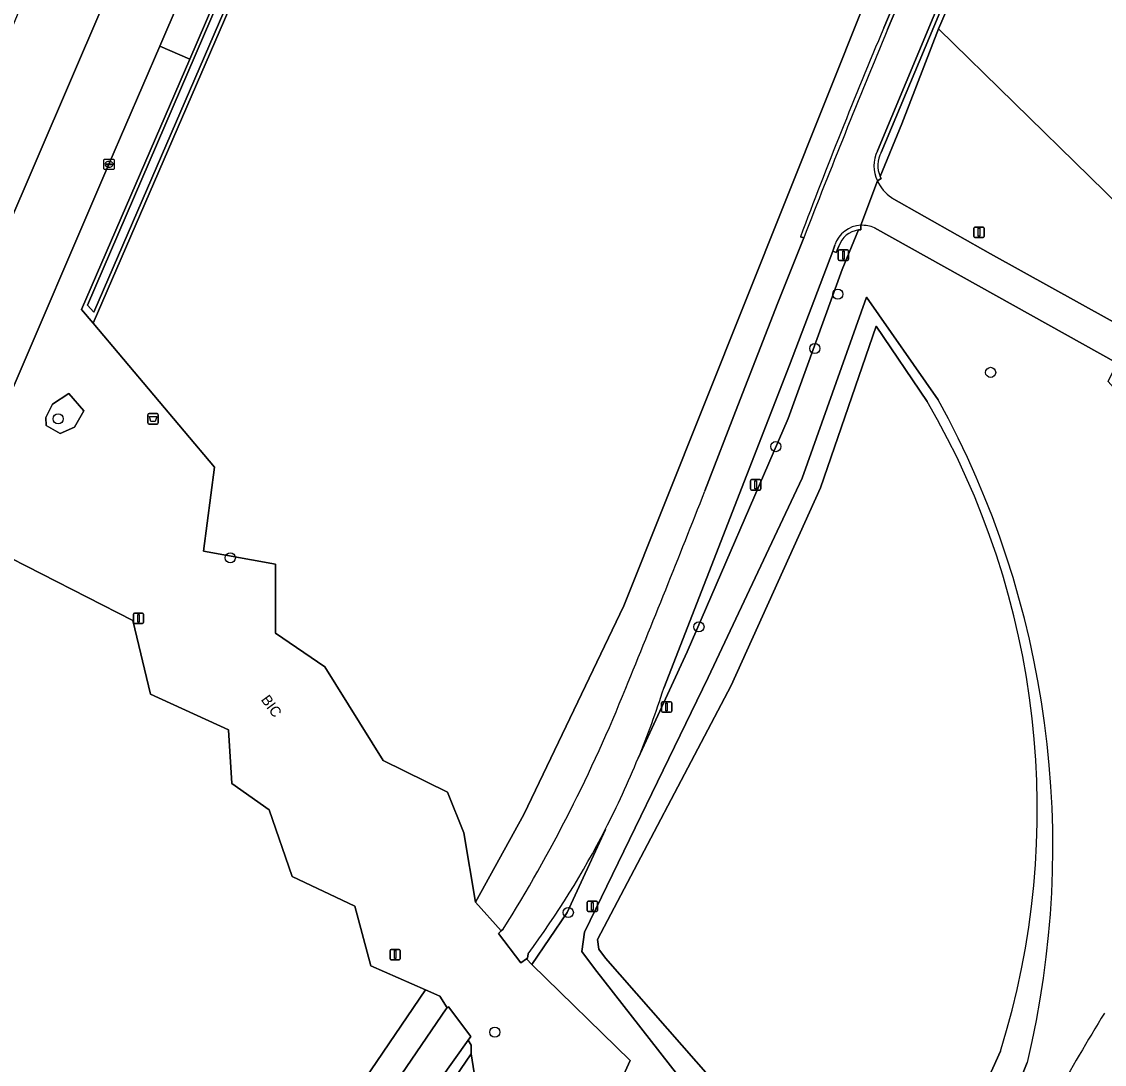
# Model space of a CAD drawing. Extents: x 155209 to 156748, y 385356 to 388487.
# Drawn here: x 155935.8 to 156040.2, y 385937.7 to 386038.3 of the extents above; entities that cross this region are included whole.
import ezdxf

# ---------------------------------------------------------------- set-up
doc = ezdxf.new("R2010")
doc.units = 0
for name, color, linetype in [('IMGEO_Afvalbak', 7, 'Continuous'), ('IMGEO_Berm_groen', 7, 'Continuous'), ('IMGEO_Berm_open', 7, 'Continuous'), ('IMGEO_Boom', 7, 'Continuous'), ('IMGEO_Fietspad_gesloten', 7, 'Continuous'), ('IMGEO_Groenvoorziening', 7, 'Continuous'), ('IMGEO_Kolk', 7, 'Continuous'), ('IMGEO_Lichtmast', 7, 'Continuous'), ('IMGEO_Loofbos', 7, 'Continuous'), ('IMGEO_Meer_plas_ven_vijver', 7, 'Continuous'), ('IMGEO_Naaldbos', 7, 'Continuous'), ('IMGEO_Oever', 7, 'Continuous'), ('IMGEO_Openbare_ruimte_label', 7, 'Continuous'), ('IMGEO_Rijbaan_lokaal_gesloten', 7, 'Continuous'), ('IMGEO_Voetpad_gesloten', 7, 'Continuous'), ('IMGEO_Voetpad_open', 7, 'Continuous'), ('IMGEO_Waterloop', 7, 'Continuous')]:
    doc.layers.add(name, color=color, linetype=linetype)

msp = doc.modelspace()

# ---------------------------------------------------------------- linework, layer by layer
at = {"layer": 'IMGEO_Afvalbak'}
for p, q in [((155948, 385999.57), (155948, 386000.37)), ((155948, 386000.37), (155948, 385999.57)), ((155948.1, 386000.47), (155948.89, 386000.47)), ((155948.89, 386000.47), (155948.1, 386000.47)), ((155948.99, 386000.37), (155948.99, 385999.57)), ((155948.99, 385999.57), (155948.99, 386000.37)), ((155948.89, 385999.47), (155948.1, 385999.47)), ((155948.1, 385999.47), (155948.89, 385999.47))]:
    msp.add_line(p, q, dxfattribs=at)
msp.add_lwpolyline([(155948.14, 386000.18), (155948.85, 386000.18), (155948.7, 385999.71), (155948.29, 385999.71), (155948.14, 386000.18)], dxfattribs=at)
for centre, start, end in [((155948.1, 386000.37), 90, 180), ((155948.1, 386000.37), 90, 180), ((155948.89, 386000.37), 0, 90), ((155948.89, 386000.37), 360, 90), ((155948.1, 385999.57), 180, 270), ((155948.1, 385999.57), 180, 270), ((155948.89, 385999.57), 270, 0), ((155948.89, 385999.57), 270, 0)]:
    msp.add_arc(centre, 0.1, start, end, dxfattribs=at)
at = {"layer": 'IMGEO_Berm_groen'}
for points in [[(156017.72, 386241.8), (155997.34, 386192.47), (155999.28, 386187.65), (155999.02, 386187.05), (155959.3, 386096.17), (155916.98, 385994.93), (155916.27, 385993.23), (155920.08, 385991.51), (155920.81, 385993.21), (155925.38, 386003.82), (155927.74, 386002.82), (155959.53, 386076.88), (155989.7, 386147.22), (156003.54, 386179.53)], [(156049.55, 386158.86), (156049.35, 386159.56), (156025.31, 386175.19), (156018.61, 386179.53), (156012.19, 386182.98), (156009.84, 386177.42), (156009.58, 386176.82), (155984.91, 386119.23), (155965.64, 386074.34), (155949.14, 386035.92), (155952.02, 386034.68), (156000, 386146)], [(156018.62, 386023.35), (156020.7, 386028.43), (156024.22, 386037.59), (156045.81, 386087.34), (156049.5, 386095.21), (156057.59, 386112.46), (156071.11, 386138.48), (156074.02, 386139.6), (156094.02, 386125.25), (156093.82, 386127.35), (156092.18, 386130.24), (156078.71, 386139.75)], [(156042.89, 386082.44), (156038.86, 386073.22), (156030.85, 386054.72), (156018.71, 386025.67)], [(156027.62, 386063.6), (156017.22, 386040.43), (155993.88, 385981.94), (155984.26, 385961.78), (155979.58, 385953.33), (155982.07, 385950.57), (155982.25, 385950.72)], [(156018.96, 386037.69), (156023.47, 386048.35), (156027.93, 386058.88), (156029.15, 386061.75), (156028.19, 386062.62), (156028.36, 386063)], [(156008.73, 386011.15), (156011.24, 386017.42), (156010.92, 386017.54)], [(156001.71, 385993.01), (156004.89, 386001.24), (156008.73, 386011.15)], [(155959.49, 385917.6), (155967.71, 385929.79), (155976.74, 385943.04), (155976.86, 385943.15), (155976.15, 385944.26), (155974.75, 385944.88), (155932.5, 385882.64), (155851.64, 385797.46), (155851.5, 385797.12)], [(155921.77, 385861.19), (155942.45, 385883.84), (155948.49, 385892.6), (155963.23, 385915.28), (155979.15, 385938.71), (155979.16, 385939.55), (155978.86, 385940.02), (155970.6, 385928.4), (155962.17, 385915.88)]]:
    msp.add_lwpolyline(points, dxfattribs=at)
for centre, radius, start, end in [((156557.9, 385810.82), 584.75, 157.17081, 159.29698), ((156020.96, 386024.42), 2.58, 151.0324, 204.678), ((154574.46, 386555.24), 1534, 337.73306, 338.49917), ((155857.09, 386028.96), 147.6, 327.9903, 338.127)]:
    msp.add_arc(centre, radius, start, end, dxfattribs=at)
at = {"layer": 'IMGEO_Berm_open'}
for points in [[(156042.51, 386082.62), (156038.47, 386073.36), (156030.47, 386054.89), (156018.34, 386025.82)], [(156018.71, 386025.67), (156030.85, 386054.72), (156038.86, 386073.22), (156042.89, 386082.44)], [(156038.35, 386082.83), (156032.91, 386070.46), (156031.37, 386069.88), (156031.03, 386069.11), (156028.36, 386063), (156028.19, 386062.62), (156029.15, 386061.75), (156027.93, 386058.88), (156023.47, 386048.35), (156018.96, 386037.69)], [(156019.32, 386037.52), (156023.82, 386048.16), (156029.56, 386061.6)], [(156018.34, 386022.93), (156018.71, 386023.16), (156018.62, 386023.35)], [(156016.51, 386018.2), (156016.74, 386018.21), (156016.74, 386018.64)], [(156010.92, 386017.54), (156011.24, 386017.42)], [(156014.25, 386016.74), (156014.04, 386016.16), (156014.36, 386016.03), (156014.61, 386016.62)]]:
    msp.add_lwpolyline(points, dxfattribs=at)
for centre, radius, start, end in [((156557.9, 385810.82), 584.75, 157.17081, 159.29698), ((156846.13, 385693.33), 895.59, 157.39848, 158.78459), ((156021.18, 386024.38), 3.18, 153.107, 207.1309), ((156020.96, 386024.42), 2.58, 151.0324, 204.678), ((156016.88, 386015.88), 2.77, 92.869, 161.8512), ((156016.82, 386015.89), 2.32, 97.6097, 161.8767)]:
    msp.add_arc(centre, radius, start, end, dxfattribs=at)
at = {"layer": 'IMGEO_Boom'}
for centre in [(156014.53, 386012), (156012.3, 386006.76), (156029.26, 386004.45), (155939.34, 385999.97), (156008.55, 385997.29), (155955.94, 385986.56), (156001.13, 385979.9), (155988.53, 385952.34), (155981.44, 385940.79)]:
    msp.add_circle(centre, 0.489, dxfattribs=at)
at = {"layer": 'IMGEO_Fietspad_gesloten'}
msp.add_lwpolyline([(155962.17, 385915.88), (155970.6, 385928.4), (155978.86, 385940.02), (155979.13, 385940.39), (155976.97, 385943.25), (155976.86, 385943.15), (155976.74, 385943.04), (155967.71, 385929.79), (155959.49, 385917.6)], dxfattribs=at)
at = {"layer": 'IMGEO_Groenvoorziening'}
for points in [[(156024.22, 386037.59), (156020.7, 386028.43), (156018.62, 386023.35), (156018.71, 386023.16), (156018.34, 386022.93)], [(156019.69, 386021.3), (156029.26, 386015.9), (156063.85, 385996.7), (156068.01, 385994.76), (156024.22, 386037.59)], [(156016.74, 386018.64), (156016.74, 386018.21), (156016.51, 386018.2), (156014.95, 386014.37), (156009.75, 386000), (156000, 385977.48), (155995.28, 385967.24)], [(156014.95, 386014.37), (156016.51, 386018.2)], [(156063.23, 385980.59), (156054.24, 385988.21), (156040.58, 386003.57), (156041.46, 386005.34), (156018.05, 386018.4)], [(156014.61, 386016.62), (156014.36, 386016.03), (156014.04, 386016.16), (156009.86, 386005.14), (155997.73, 385973.97)], [(155995.28, 385967.24), (156000, 385977.48), (156009.75, 386000), (156014.95, 386014.37)], [(155991.07, 385946.93), (155989.85, 385948.58), (155990.11, 385950.43), (156002.03, 385975.02), (156011.1, 385994.24), (156017.28, 386011.72), (156024.21, 386001.79)], [(155984.67, 385948.36), (155984.61, 385947.94), (155984.51, 385947.86), (155985, 385947.32), (155988.41, 385952.34), (155992.11, 385960.36)], [(155992.11, 385960.36), (155988.41, 385952.34), (155985, 385947.32), (155994.5, 385938.05), (155993.71, 385936.3), (155994.61, 385935.3), (155997.57, 385935.14), (156002.22, 385930.59), (156002.75, 385928.69), (156005.3, 385926.18), (156005.3, 385921.16), (156008.31, 385921.43), (156018.53, 385908.45), (156017.52, 385906.07), (156019.47, 385903.8), (156024.23, 385912.36), (156030.93, 385926.22)], [(156032.79, 385937.86), (156028.97, 385928.22), (156019.92, 385909.95), (155991.07, 385946.93)], [(155979.82, 385934.62), (155979.15, 385938.71), (155963.23, 385915.28)]]:
    msp.add_lwpolyline(points, dxfattribs=at)
msp.add_lwpolyline([(155938.14, 386000.11), (155938.18, 385999.31), (155939.52, 385998.54), (155940.93, 385999.18), (155941.83, 386000.74), (155940.36, 386002.4), (155938.8, 386001.39)], close=True, dxfattribs=at)
for centre, radius, start, end in [((156021.87, 386024.48), 3.85, 203.6198, 235.4213), ((156016.88, 386015.69), 2.95, 66.5786, 92.6733), ((156016.82, 386015.89), 2.32, 97.6097, 161.8767), ((155945.74, 385958.71), 89.52, 346.5304, 28.7684), ((155913.88, 386000.64), 87.99, 337.6916, 342.3572), ((155913.43, 386000.81), 88.46, 332.7924, 337.6986), ((155913.4, 386000.83), 88.5, 323.6332, 332.7845), ((156291.79, 385789.4), 294.56, 148.6534, 152.3219)]:
    msp.add_arc(centre, radius, start, end, dxfattribs=at)
at = {"layer": 'IMGEO_Kolk'}
for p, q in [((155943.74, 386024.1), (155943.74, 386024.95)), ((155943.81, 386025.03), (155944.67, 386025.03)), ((155944.23, 386024.81), (155944.25, 386024.81)), ((155944.74, 386024.95), (155944.74, 386024.1)), ((155944.67, 386024.03), (155943.81, 386024.03)), ((155944, 386024.52), (155944, 386024.53)), ((155944.04, 386024.57), (155944.44, 386024.57)), ((155944.44, 386024.48), (155944.04, 386024.48)), ((155944.25, 386024.25), (155944.23, 386024.25)), ((155944.48, 386024.53), (155944.48, 386024.52))]:
    msp.add_line(p, q, dxfattribs=at)
for points in [[(155943.74, 386024.1), (155943.74, 386024.95)], [(155943.81, 386025.03), (155944.67, 386025.03)], [(155944.74, 386024.95), (155944.74, 386024.1)], [(155944.67, 386024.03), (155943.81, 386024.03)]]:
    msp.add_lwpolyline(points, dxfattribs=at)
for centre, radius, start, end in [((155943.82, 386024.95), 0.0765, 91.552, 178.448), ((155943.82, 386024.95), 0.0765, 91.552, 178.448), ((155944.66, 386024.95), 0.0765, 1.552, 88.448), ((155944.66, 386024.95), 0.0765, 1.552, 88.448), ((155943.82, 386024.1), 0.0765, 181.552, 268.448), ((155943.82, 386024.1), 0.0765, 181.552, 268.448), ((155944.04, 386024.53), 0.0403, 85.8775, 175.7526), ((155944.04, 386024.52), 0.0366, 178.938, 274.7102), ((155944.44, 386024.53), 0.0386, 1.7309, 96.639), ((155944.44, 386024.53), 0.043, 264.8664, 352.4533), ((155944.66, 386024.1), 0.0765, 271.552, 358.448), ((155944.66, 386024.1), 0.0765, 271.552, 358.448)]:
    msp.add_arc(centre, radius, start, end, dxfattribs=at)
for centre, major_axis, ratio, start_param, end_param in [((155944.23, 386024.53), (-0.387, 0.002), 0.722429, 4.712389, 7.853982), ((155944.25, 386024.53), (-0.39, 0.002), 0.717154, 1.570796, 4.712389)]:
    msp.add_ellipse(centre, major_axis=major_axis, ratio=ratio, start_param=start_param, end_param=end_param, dxfattribs=at)
at = {"layer": 'IMGEO_Lichtmast'}
for p, q in [((156027.64, 386017.57), (156027.64, 386018.37)), ((156027.64, 386018.37), (156027.64, 386017.57)), ((156027.74, 386018.47), (156028.53, 386018.47)), ((156028.53, 386018.47), (156027.74, 386018.47)), ((156028.53, 386017.47), (156027.74, 386017.47)), ((156027.74, 386017.47), (156028.53, 386017.47)), ((156028.63, 386018.37), (156028.63, 386017.57)), ((156028.63, 386017.57), (156028.63, 386018.37)), ((156014.57, 386015.36), (156014.57, 386016.16)), ((156014.57, 386016.16), (156014.57, 386015.36)), ((156014.67, 386016.26), (156015.46, 386016.26)), ((156015.46, 386016.26), (156014.67, 386016.26)), ((156015.56, 386016.16), (156015.56, 386015.36)), ((156015.56, 386015.36), (156015.56, 386016.16)), ((156015.46, 386015.26), (156014.67, 386015.26)), ((156014.67, 386015.26), (156015.46, 386015.26)), ((156006.11, 385993.2), (156006.11, 385994)), ((156006.11, 385994), (156006.11, 385993.2)), ((156006.21, 385994.1), (156007, 385994.1)), ((156007, 385994.1), (156006.21, 385994.1)), ((156007.1, 385994), (156007.1, 385993.2)), ((156007.1, 385993.2), (156007.1, 385994)), ((156007, 385993.1), (156006.21, 385993.1)), ((156006.21, 385993.1), (156007, 385993.1)), ((155946.59, 385980.31), (155946.59, 385981.11)), ((155946.59, 385981.11), (155946.59, 385980.31)), ((155946.69, 385981.21), (155947.48, 385981.21)), ((155947.48, 385981.21), (155946.69, 385981.21)), ((155947.58, 385981.11), (155947.58, 385980.31)), ((155947.58, 385980.31), (155947.58, 385981.11)), ((155947.48, 385980.21), (155946.69, 385980.21)), ((155946.69, 385980.21), (155947.48, 385980.21)), ((155997.51, 385971.77), (155997.51, 385972.57)), ((155997.51, 385972.57), (155997.51, 385971.77)), ((155997.61, 385972.67), (155998.4, 385972.67)), ((155998.4, 385972.67), (155997.61, 385972.67)), ((155998.5, 385972.57), (155998.5, 385971.77)), ((155998.5, 385971.77), (155998.5, 385972.57)), ((155998.4, 385971.67), (155997.61, 385971.67)), ((155997.61, 385971.67), (155998.4, 385971.67)), ((155990.35, 385952.54), (155990.35, 385953.34)), ((155990.35, 385953.34), (155990.35, 385952.54)), ((155990.45, 385953.44), (155991.24, 385953.44)), ((155991.24, 385953.44), (155990.45, 385953.44)), ((155991.34, 385953.34), (155991.34, 385952.54)), ((155991.34, 385952.54), (155991.34, 385953.34)), ((155991.24, 385952.44), (155990.45, 385952.44)), ((155990.45, 385952.44), (155991.24, 385952.44)), ((155971.34, 385947.88), (155971.34, 385948.68)), ((155971.34, 385948.68), (155971.34, 385947.88)), ((155971.44, 385948.78), (155972.23, 385948.78)), ((155972.23, 385948.78), (155971.44, 385948.78)), ((155972.33, 385948.68), (155972.33, 385947.88)), ((155972.33, 385947.88), (155972.33, 385948.68)), ((155972.23, 385947.78), (155971.44, 385947.78)), ((155971.44, 385947.78), (155972.23, 385947.78))]:
    msp.add_line(p, q, dxfattribs=at)
for points in [[(156028.06, 386018.35), (156028.21, 386018.35), (156028.21, 386017.6), (156028.06, 386017.6), (156028.06, 386018.35)], [(156014.99, 386016.13), (156015.14, 386016.13), (156015.14, 386015.38), (156014.99, 386015.38), (156014.99, 386016.13)], [(156006.53, 385993.98), (156006.68, 385993.98), (156006.68, 385993.23), (156006.53, 385993.23), (156006.53, 385993.98)], [(155947.01, 385981.09), (155947.16, 385981.09), (155947.16, 385980.34), (155947.01, 385980.34), (155947.01, 385981.09)], [(155997.93, 385972.54), (155998.08, 385972.54), (155998.08, 385971.79), (155997.93, 385971.79), (155997.93, 385972.54)], [(155990.77, 385953.31), (155990.92, 385953.31), (155990.92, 385952.56), (155990.77, 385952.56), (155990.77, 385953.31)], [(155971.76, 385948.66), (155971.91, 385948.66), (155971.91, 385947.91), (155971.76, 385947.91), (155971.76, 385948.66)]]:
    msp.add_lwpolyline(points, dxfattribs=at)
for centre, start, end in [((156027.74, 386018.37), 90, 180), ((156027.74, 386018.37), 90, 180), ((156027.74, 386017.57), 180, 270), ((156027.74, 386017.57), 180, 270), ((156028.53, 386018.37), 0, 90), ((156028.53, 386018.37), 360, 90), ((156028.53, 386017.57), 270, 0), ((156028.53, 386017.57), 270, 0), ((156014.67, 386016.16), 90, 180), ((156014.67, 386016.16), 90, 180), ((156014.67, 386015.36), 180, 270), ((156014.67, 386015.36), 180, 270), ((156015.46, 386016.16), 0, 90), ((156015.46, 386016.16), 360, 90), ((156015.46, 386015.36), 270, 0), ((156015.46, 386015.36), 270, 0), ((156006.21, 385994), 90, 180), ((156006.21, 385994), 90, 180), ((156007, 385994), 0, 90), ((156007, 385994), 360, 90), ((156006.21, 385993.2), 180, 270), ((156006.21, 385993.2), 180, 270), ((156007, 385993.2), 270, 0), ((156007, 385993.2), 270, 0), ((155946.69, 385981.11), 90, 180), ((155946.69, 385981.11), 90, 180), ((155947.48, 385981.11), 0, 90), ((155947.48, 385981.11), 360, 90), ((155946.69, 385980.31), 180, 270), ((155946.69, 385980.31), 180, 270), ((155947.48, 385980.31), 270, 0), ((155947.48, 385980.31), 270, 0), ((155997.61, 385972.57), 90, 180), ((155997.61, 385972.57), 90, 180), ((155998.4, 385972.57), 0, 90), ((155998.4, 385972.57), 360, 90), ((155997.61, 385971.77), 180, 270), ((155997.61, 385971.77), 180, 270), ((155998.4, 385971.77), 270, 0), ((155998.4, 385971.77), 270, 0), ((155990.45, 385953.34), 90, 180), ((155990.45, 385953.34), 90, 180), ((155991.24, 385953.34), 0, 90), ((155991.24, 385953.34), 360, 90), ((155990.45, 385952.54), 180, 270), ((155990.45, 385952.54), 180, 270), ((155991.24, 385952.54), 270, 0), ((155991.24, 385952.54), 270, 0), ((155971.44, 385948.68), 90, 180), ((155971.44, 385948.68), 90, 180), ((155972.23, 385948.68), 0, 90), ((155972.23, 385948.68), 360, 90), ((155971.44, 385947.88), 180, 270), ((155971.44, 385947.88), 180, 270), ((155972.23, 385947.88), 270, 0), ((155972.23, 385947.88), 270, 0)]:
    msp.add_arc(centre, 0.1, start, end, dxfattribs=at)
at = {"layer": 'IMGEO_Loofbos'}
msp.add_lwpolyline([(156074.43, 386077.96), (156078.82, 386083.96), (156095.72, 386107.6), (156094.02, 386125.25), (156074.02, 386139.6), (156071.11, 386138.48), (156057.59, 386112.46), (156049.5, 386095.21), (156045.81, 386087.34), (156024.22, 386037.59), (156068.01, 385994.76)], dxfattribs=at)
at = {"layer": 'IMGEO_Meer_plas_ven_vijver'}
for points in [[(156023.13, 386001.65), (156018.22, 386008.91), (156012.86, 385993.3), (156004.23, 385974.24), (155991.34, 385949.73), (155991.49, 385948.79), (155992.11, 385947.95)], [(155992.11, 385947.95), (156018.56, 385917.78), (156025.62, 385928.76), (156030.21, 385938.97)]]:
    msp.add_lwpolyline(points, dxfattribs=at)
msp.add_arc((155955.43, 385962.27), 78.33, 342.6984, 30.1872, dxfattribs=at)
at = {"layer": 'IMGEO_Naaldbos'}
for points in [[(156017.22, 386040.43), (156013.69, 386043.98), (156001.7, 386056.03), (156000, 386057.99), (155979.68, 386081.47), (155975.71, 386085.5), (155942.72, 386009.19), (155954.43, 385995.3), (155953.35, 385987.2), (155960.31, 385985.94), (155960.31, 385979.29), (155965.05, 385976.04), (155970.69, 385967), (155976.88, 385963.96), (155978.47, 385960.03), (155979.58, 385953.33), (155984.26, 385961.78), (155993.88, 385981.94)], [(155974.75, 385944.88), (155969.49, 385947.2), (155967.94, 385952.96), (155961.9, 385955.8), (155959.69, 385962.26), (155956.09, 385964.8), (155955.77, 385969.98), (155948.24, 385973.41), (155946.55, 385980.5), (155933.29, 385987.26), (155871.9, 385843.96), (155870.19, 385841.27), (155853.47, 385801.77), (155851.64, 385797.46), (155932.5, 385882.64)]]:
    msp.add_lwpolyline(points, close=True, dxfattribs=at)
at = {"layer": 'IMGEO_Oever'}
for points in [[(156015.54, 386179.18), (156015.76, 386179.19), (156015.84, 386179.15), (156015.91, 386178.56), (156028.73, 386169.96), (156048.81, 386156.86), (156048.58, 386156.51), (156048.41, 386156.24), (156033.05, 386166.23), (156015.52, 386177.85), (156015.03, 386177.92), (156014.67, 386177.6), (156000.35, 386144.53), (155999.67, 386142.97), (155975.09, 386085.85), (155975.31, 386085.48), (155942.79, 386010.26)], [(156013.5, 386177.7), (156000, 386146), (155952.02, 386034.68), (155941.6, 386010.52), (155942.72, 386009.19), (155975.71, 386085.5), (155975.49, 386085.88), (156000, 386142.83)], [(155942.79, 386010.26), (155942.16, 386010.92), (156000.33, 386145.86), (156013.83, 386177.55)], [(156024.21, 386001.79), (156017.28, 386011.72), (156011.1, 385994.24), (156002.03, 385975.02), (155990.11, 385950.43), (155989.85, 385948.58), (155991.07, 385946.93)], [(155992.11, 385947.95), (155991.49, 385948.79), (155991.34, 385949.73), (156004.23, 385974.24), (156012.86, 385993.3), (156018.22, 386008.91), (156023.13, 386001.65)], [(156030.21, 385938.97), (156025.62, 385928.76), (156018.56, 385917.78), (155992.11, 385947.95)], [(155991.07, 385946.93), (156019.92, 385909.95), (156028.97, 385928.22), (156032.79, 385937.86)]]:
    msp.add_lwpolyline(points, dxfattribs=at)
for centre, radius, start, end in [((155945.74, 385958.71), 89.52, 346.5304, 28.7684), ((155955.43, 385962.27), 78.33, 342.6984, 30.1872)]:
    msp.add_arc(centre, radius, start, end, dxfattribs=at)
at = {"layer": 'IMGEO_Rijbaan_lokaal_gesloten'}
for points in [[(155944.24, 386024.53), (155949.14, 386035.92), (155965.64, 386074.34), (155984.91, 386119.23), (156009.58, 386176.82), (156003.54, 386179.53), (155989.7, 386147.22), (155959.53, 386076.88), (155927.74, 386002.82), (155923, 385991.79), (155918.96, 385982.46), (155913.39, 385969.48), (155908.98, 385959.23), (155875.91, 385882.64)], [(156018.34, 386025.82), (156030.47, 386054.89), (156038.47, 386073.36), (156042.51, 386082.62)], [(156038.74, 386082.69), (156029.56, 386061.6), (156023.82, 386048.16), (156019.32, 386037.52)], [(155882.02, 385879.97), (155929.14, 385989.38), (155934.02, 386000.73), (155944.24, 386024.53)], [(156016.74, 386018.64), (156018.34, 386022.93)], [(155997.73, 385973.97), (156009.86, 386005.14), (156014.04, 386016.16), (156014.25, 386016.74)], [(156011.24, 386017.42), (156008.73, 386011.15), (156004.89, 386001.24), (156001.71, 385993.01)], [(155982.25, 385950.72), (155982.07, 385950.57), (155981.81, 385950.33), (155983.96, 385947.49), (155984.51, 385947.86), (155984.61, 385947.94), (155984.67, 385948.36)]]:
    msp.add_lwpolyline(points, dxfattribs=at)
for centre, radius, start, end in [((156846.13, 385693.33), 895.59, 157.39848, 158.78459), ((156021.18, 386024.38), 3.18, 153.107, 207.1309), ((156016.88, 386015.88), 2.77, 92.869, 161.8512), ((154574.46, 386555.24), 1534, 337.73306, 338.49917), ((155857.09, 386028.96), 147.6, 327.9903, 338.127), ((155913.88, 386000.64), 87.99, 337.6916, 342.3572), ((155913.43, 386000.81), 88.46, 332.7924, 337.6986), ((155913.4, 386000.83), 88.5, 323.6332, 332.7845)]:
    msp.add_arc(centre, radius, start, end, dxfattribs=at)
at = {"layer": 'IMGEO_Voetpad_gesloten'}
for points in [[(156018.34, 386022.93), (156016.74, 386018.64)], [(156068.01, 385994.76), (156063.85, 385996.7), (156029.26, 386015.9), (156019.69, 386021.3)], [(156018.05, 386018.4), (156041.46, 386005.34), (156064.33, 385992.59)]]:
    msp.add_lwpolyline(points, dxfattribs=at)
for centre, radius, start, end in [((156021.87, 386024.48), 3.85, 203.6198, 235.4213), ((156016.88, 386015.69), 2.95, 66.5786, 92.6733), ((156291.79, 385789.4), 294.56, 148.6534, 152.3219)]:
    msp.add_arc(centre, radius, start, end, dxfattribs=at)
at = {"layer": 'IMGEO_Voetpad_open'}
for points in [[(155978.47, 385960.03), (155976.88, 385963.96), (155970.69, 385967), (155965.05, 385976.04), (155960.31, 385979.29), (155960.31, 385985.94), (155953.35, 385987.2), (155954.43, 385995.3), (155942.72, 386009.19), (155941.6, 386010.52), (155952.02, 386034.68), (155949.14, 386035.92), (155944.24, 386024.53), (155934.02, 386000.73)], [(155933.29, 385987.26), (155946.55, 385980.5), (155948.24, 385973.41), (155955.77, 385969.98), (155956.09, 385964.8), (155959.69, 385962.26), (155961.9, 385955.8), (155967.94, 385952.96), (155969.49, 385947.2), (155974.75, 385944.88), (155976.15, 385944.26), (155976.86, 385943.15), (155976.97, 385943.25), (155979.13, 385940.39), (155978.86, 385940.02), (155979.16, 385939.55), (155979.15, 385938.71), (155979.82, 385934.62)], [(156021.25, 385898.67), (156018.65, 385902.04), (156018.56, 385902.16), (156019.47, 385903.8), (156017.52, 385906.07), (156018.53, 385908.45), (156008.31, 385921.43), (156005.3, 385921.16), (156005.3, 385926.18), (156002.75, 385928.69), (156002.22, 385930.59), (155997.57, 385935.14), (155994.61, 385935.3), (155993.71, 385936.3), (155994.5, 385938.05), (155985, 385947.32), (155984.51, 385947.86), (155983.96, 385947.49), (155981.81, 385950.33), (155982.07, 385950.57), (155979.58, 385953.33), (155978.47, 385960.03)]]:
    msp.add_lwpolyline(points, dxfattribs=at)
msp.add_lwpolyline([(155938.18, 385999.31), (155938.14, 386000.11), (155938.8, 386001.39), (155940.36, 386002.4), (155941.83, 386000.74), (155940.93, 385999.18), (155939.52, 385998.54)], close=True, dxfattribs=at)
at = {"layer": 'IMGEO_Waterloop'}
msp.add_lwpolyline([(156013.83, 386177.55), (156000.33, 386145.86), (155942.16, 386010.92), (155942.79, 386010.26), (155975.31, 386085.48), (155975.09, 386085.85), (155999.67, 386142.97), (156000.35, 386144.53), (156014.67, 386177.6), (156015.03, 386177.92), (156015.52, 386177.85), (156033.05, 386166.23), (156048.41, 386156.24), (156048.58, 386156.51), (156048.81, 386156.86), (156028.73, 386169.96), (156015.91, 386178.56), (156015.84, 386179.15), (156015.76, 386179.19), (156015.54, 386179.18)], dxfattribs=at)

# ---------------------------------------------------------------- texts
at = {"layer": 'IMGEO_Openbare_ruimte_label'}
msp.add_text('BIC', height=1, rotation=306.0105, dxfattribs=at).set_placement((155958.85, 385972.87))

doc.saveas('drawing.dxf')
